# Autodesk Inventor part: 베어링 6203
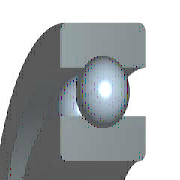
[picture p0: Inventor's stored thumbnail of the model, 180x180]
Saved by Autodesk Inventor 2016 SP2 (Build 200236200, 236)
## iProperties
IsCustomPart: 1
Created: 2012-02
Part Number: 베어링 6203
Material: 강철, 연강
Description: 깊은 그루브 볼 베어링
Document SubType Name: Modeling
Standard: KS B 2023
Designer: mduedu
Standards Organization: KS
Language: ko-KR
Size Designation: 6203 - 17 x 40 x 12
Categories: <MemberInstance><Categories><Category DisplayName="샤프트 부품" InternalName="7f7aeb1f-a693-4053-b835-cee3144e0d98" Mnemonic="SHFT"><Category DisplayName="베어링" Inter
Density: 1 g/cm^3
Appearance: 노란색
Author: mduedu
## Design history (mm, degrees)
sketch "스케치" dims "d0" = 5.98 (= -0.26 x WD + 0.26 x BD)
  geometry: L1 (3.01, 14.25)-(8.99, 14.25); L2 (6, 14.25)-(6, 11.26); L3 (6, 14.25)-(6, 17.24); L4 (3.778, 12.249)-(0, 12.249); L5 (0, 8.5)-(12, 8.5); L6 (3.778, 16.251)-(0, 16.251); L7 (0, 20)-(12, 20); L8 (12, 8.5)-(12, 12.249); L9 (8.222, 12.249)-(12, 12.249); L10 (8.222, 16.251)-(12, 16.251); L11 (12, 20)-(12, 16.251); L12 (-1.4, 0)-(8.4, 0) reference; L13 (0, -0.3)-(0, 5.3) reference
  constraints: 22 end point, 4 point on line, 2 collinear, 2 perpendicular, 2 symmetric about line, 1 midpoint, 1 parallel, 14 other
  dimensions: "d9" = 17 diameter of L5 L12 (= WD); "d11" = 40 diameter of L7 L12 (= BD); "d12" = 12 distance between parallel lines of L8 L13 (= KB); "d13" = 24.498 diameter of L9 L12 (= 0.326 x BD + 0.674 x WD)
revolve "본체" stored, may be unused: angle "d6" = 90 deg
revolve "볼" stored, may be unused: angle "d7" = 90 deg
pattern_circular "IDS_ARRAYBALL[SIMPL:T]" dims angle "d3" = 360 deg
body "Solid1"
fillet "모깎기1" dims "d1" = 0.6 (= KRS)
other parameters: "WD" = 17 [user parameter; used in 5 equation terms], "BD" = 40 [user parameter; used in 5 equation terms], "KB" = 12 [user parameter; used in 1 equation term], "KRS" = 0.6 [user parameter; used in 1 equation term], "d4" = 0, "d5" = 0, "d8" = 0, "d14" = 0, "d15" = 0, "BBA" = 0 [user parameter], "BC0" = 4750000 [user parameter], "BC" = 9560000 [user parameter], "WR" = 8.5 (= 0.5 x WD) [user parameter]
